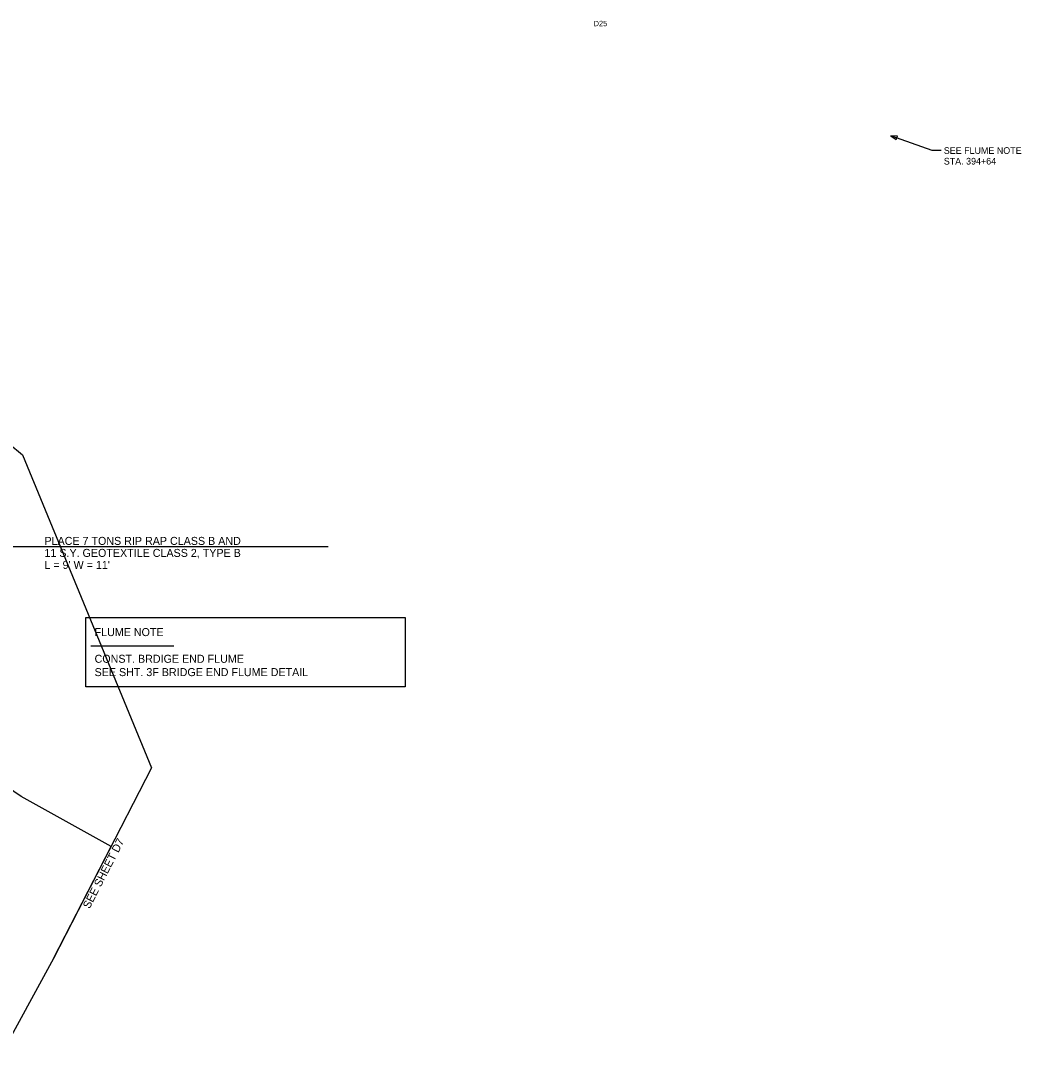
# Model space of a CAD drawing. Extents: x 1608789 to 1610795, y 1093162 to 1094361.
# Drawn here: x 1610045 to 1610795, y 1093583 to 1094361 of the extents above; entities that cross this region are included whole.
import ezdxf

# ---------------------------------------------------------------- set-up
doc = ezdxf.new("R2010")
doc.units = 0
for name, color, linetype in [('NOI', 7, 'Continuous'), ('Plan_Clip', 7, 'Continuous'), ('RD_SHT_Bndy', 7, 'Continuous'), ('RD_SHT_MatchLine', 7, 'Continuous'), ('RD_TX_Drainage', 7, 'Continuous')]:
    doc.layers.add(name, color=color, linetype=linetype)

msp = doc.modelspace()

# ---------------------------------------------------------------- linework, layer by layer
at = {"layer": 'NOI'}
msp.add_lwpolyline([(1610094.18, 1093913.79), (1610333.44, 1093913.79), (1610333.44, 1093861.94), (1610094.18, 1093861.94)], close=True, dxfattribs=at)
at = {"layer": 'Plan_Clip'}
for points in [[(1609408.82, 1094333.76), (1609476.05, 1094319.7), (1609758.48, 1094161.88), (1609754.93, 1094133.63), (1609777.73, 1094121.71), (1609844.69, 1094114.18), (1609913.32, 1094146.13), (1610046.84, 1094035.59), (1610143.39, 1093801.2), (1610070, 1093658.12), (1610028.96, 1093583.46), (1609859.36, 1093621.37), (1609735.98, 1093652.25), (1609733.52, 1093664.22), (1609633.89, 1093646.58), (1609414.5, 1093602.61), (1609098.34, 1093762.73), (1609319.26, 1094082.92), (1609389.72, 1094179.44), (1609353.45, 1094193.74), (1609387.82, 1094283.49)], [(1609408.82, 1094333.76), (1609476.05, 1094319.7), (1609758.48, 1094161.88), (1609754.93, 1094133.63), (1609777.73, 1094121.71), (1609844.69, 1094114.18), (1609913.32, 1094146.13), (1610046.84, 1094035.59), (1610143.39, 1093801.2), (1610070, 1093658.12), (1610028.96, 1093583.46), (1609859.36, 1093621.37), (1609735.98, 1093652.25), (1609733.52, 1093664.22), (1609633.89, 1093646.58), (1609414.5, 1093602.61), (1609098.34, 1093762.73), (1609319.26, 1094082.92), (1609389.72, 1094179.44), (1609353.45, 1094193.74), (1609387.82, 1094283.49)], [(1609408.82, 1094333.76), (1609476.05, 1094319.7), (1609758.48, 1094161.88), (1609754.93, 1094133.63), (1609777.73, 1094121.71), (1609844.69, 1094114.18), (1609913.32, 1094146.13), (1610046.84, 1094035.59), (1610143.39, 1093801.2), (1610070, 1093658.12), (1610028.96, 1093583.46), (1609859.36, 1093621.37), (1609735.98, 1093652.25), (1609733.52, 1093664.22), (1609633.89, 1093646.58), (1609414.5, 1093602.61), (1609098.34, 1093762.73), (1609319.26, 1094082.92), (1609389.72, 1094179.44), (1609353.45, 1094193.74), (1609387.82, 1094283.49)], [(1609408.82, 1094333.76), (1609476.05, 1094319.7), (1609758.48, 1094161.88), (1609754.93, 1094133.63), (1609777.73, 1094121.71), (1609844.69, 1094114.18), (1609913.32, 1094146.13), (1610046.84, 1094035.59), (1610143.39, 1093801.2), (1610070, 1093658.12), (1610028.96, 1093583.46), (1609859.36, 1093621.37), (1609735.98, 1093652.25), (1609733.52, 1093664.22), (1609633.89, 1093646.58), (1609414.5, 1093602.61), (1609098.34, 1093762.73), (1609319.26, 1094082.92), (1609389.72, 1094179.44), (1609353.45, 1094193.74), (1609387.82, 1094283.49)], [(1609408.82, 1094333.76), (1609476.05, 1094319.7), (1609758.48, 1094161.88), (1609754.93, 1094133.63), (1609777.73, 1094121.71), (1609844.69, 1094114.18), (1609913.32, 1094146.13), (1610046.84, 1094035.59), (1610143.39, 1093801.2), (1610070, 1093658.12), (1610028.96, 1093583.46), (1609859.36, 1093621.37), (1609735.98, 1093652.25), (1609733.52, 1093664.22), (1609633.89, 1093646.58), (1609414.5, 1093602.61), (1609098.34, 1093762.73), (1609319.26, 1094082.92), (1609389.72, 1094179.44), (1609353.45, 1094193.74), (1609387.82, 1094283.49)], [(1609408.82, 1094333.76), (1609476.05, 1094319.7), (1609758.48, 1094161.88), (1609754.93, 1094133.63), (1609777.73, 1094121.71), (1609844.69, 1094114.18), (1609913.32, 1094146.13), (1610046.84, 1094035.59), (1610143.39, 1093801.2), (1610070, 1093658.12), (1610028.96, 1093583.46), (1609859.36, 1093621.37), (1609735.98, 1093652.25), (1609733.52, 1093664.22), (1609633.89, 1093646.58), (1609414.5, 1093602.61), (1609098.34, 1093762.73), (1609319.26, 1094082.92), (1609389.72, 1094179.44), (1609353.45, 1094193.74), (1609387.82, 1094283.49)], [(1609408.82, 1094333.76), (1609476.05, 1094319.7), (1609758.48, 1094161.88), (1609754.93, 1094133.63), (1609777.73, 1094121.71), (1609844.69, 1094114.18), (1609913.32, 1094146.13), (1610046.84, 1094035.59), (1610143.39, 1093801.2), (1610070, 1093658.12), (1610028.96, 1093583.46), (1609859.36, 1093621.37), (1609735.98, 1093652.25), (1609733.52, 1093664.22), (1609633.89, 1093646.58), (1609414.5, 1093602.61), (1609098.34, 1093762.73), (1609319.26, 1094082.92), (1609389.72, 1094179.44), (1609353.45, 1094193.74), (1609387.82, 1094283.49)], [(1609408.82, 1094333.76), (1609476.05, 1094319.7), (1609758.48, 1094161.88), (1609754.93, 1094133.63), (1609777.73, 1094121.71), (1609844.69, 1094114.18), (1609913.32, 1094146.13), (1610046.84, 1094035.59), (1610143.39, 1093801.2), (1610070, 1093658.12), (1610113.1, 1093742.16), (1610045.7, 1093779.59), (1609980.23, 1093824), (1609910.75, 1093878.22), (1609751.43, 1094013.11), (1609599.85, 1094143.63), (1609487.87, 1094208.49), (1609378.34, 1094258.75), (1609387.82, 1094283.49)]]:
    msp.add_lwpolyline(points, close=True, dxfattribs=at)
at = {"layer": 'RD_TX_Drainage'}
for p, q in [((1610275.79, 1093966.7), (1610056.72, 1093966.7)), ((1610097.84, 1093892.64), (1610160.18, 1093892.64))]:
    msp.add_line(p, q, dxfattribs=at)
for points in [[(1610735.09, 1094263.78), (1610728.38, 1094263.78), (1610697.33, 1094274.83)], [(1610056.72, 1093966.7), (1610018.3, 1093966.7), (1609969.52, 1093866.63)]]:
    msp.add_lwpolyline(points, dxfattribs=at)
msp.add_lwpolyline([(1610702.32, 1094274.43), (1610697.33, 1094274.83), (1610701.45, 1094271.99)], close=True, dxfattribs=at)

# ---------------------------------------------------------------- texts
at = {"layer": 'NOI'}
for s, p in [('FLUME NOTE', (1610100.73, 1093899.86)), ('CONST. BRDIGE END FLUME', (1610100.73, 1093879.86)), ('SEE SHT. 3F BRIDGE END FLUME DETAIL', (1610100.73, 1093869.86))]:
    msp.add_text(s, height=6, rotation=0.00149, dxfattribs=at).set_placement(p)
at = {"layer": 'RD_SHT_Bndy'}
msp.add_text('D25', height=4, dxfattribs=at).set_placement((1610474.71, 1094356.98))
at = {"layer": 'RD_SHT_MatchLine'}
msp.add_text('SEE SHEET D7', height=6, rotation=62.84804, dxfattribs=at).set_placement((1610096.92, 1093695.04))
at = {"layer": 'RD_TX_Drainage'}
for s, height, p in [('SEE FLUME NOTE', 5, (1610737.09, 1094261.28)), ('STA. 394+64', 5, (1610737.09, 1094253.28)), ('PLACE 7 TONS RIP RAP CLASS B AND', 6, (1610063.17, 1093968.2)), ('11 S.Y. GEOTEXTILE CLASS 2, TYPE B', 6, (1610063.17, 1093959.2)), ("L = 9' W = 11'", 6, (1610063.17, 1093950.2))]:
    msp.add_text(s, height=height, rotation=360, dxfattribs=at).set_placement(p)

doc.saveas('drawing.dxf')
